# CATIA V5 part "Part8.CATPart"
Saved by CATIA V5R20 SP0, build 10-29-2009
Part number: 9CS101615
Revision: ANY
Definition: UNKNOWN
Nomenclature: 9CS101615
Source: Unknown
Bounding box of the stored display mesh (mm): x -8 to 8, y -7.5 to 7.5, z -8 to 8
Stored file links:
  C:\Users\Utente\Desktop\IO LAVORO\3D X SITO CF\CUMSA\3D files PW\pw101830\pw101830_injection\Part8.CATPart
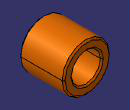
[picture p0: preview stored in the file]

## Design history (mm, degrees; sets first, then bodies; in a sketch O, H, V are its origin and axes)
Body1 "Revolución1" (main body)
  Solid1: solid without history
